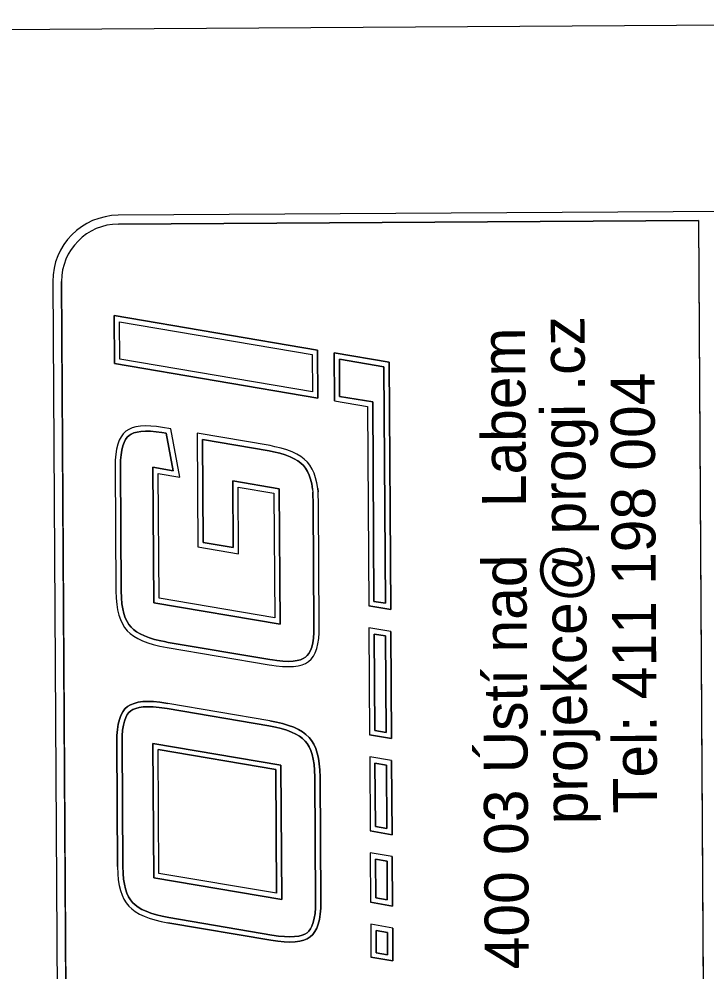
# Model space of a CAD drawing. Extents: x -735036 to -734743, y -1144813 to -1144181.
# Drawn here: x -734820.65 to -734790.92, y -1144221.87 to -1144180.65 of the extents above; entities that cross this region are included whole.
import ezdxf

# ---------------------------------------------------------------- set-up
doc = ezdxf.new("R2010")
doc.units = 0
doc.layers.add('000_rozpiska', color=7, linetype='Continuous')

# ---------------------------------------------------------------- blocks, each defined once
blk = doc.blocks.new('A$C2B726605')
at = {"layer": '000_rozpiska'}
for p, q in [((-8.894, 71.716), (-181.794, 71.716)), ((-8.894, 71.716), (-181.794, 71.716)), ((-8.894, 71.336), (-63.044, 71.336)), ((-34.759, 68.816), (-34.511, 68.836)), ((-34.511, 68.836), (-34.202, 68.844)), ((-34.202, 68.844), (-28.821, 68.844)), ((-28.821, 68.844), (-28.555, 68.837)), ((-28.555, 68.837), (-28.314, 68.816)), ((-23.536, 68.882), (-23.718, 68.8)), ((-23.336, 68.949), (-23.536, 68.882)), ((-23.113, 69), (-23.336, 68.949)), ((-22.876, 69.037), (-23.113, 69)), ((-22.611, 69.06), (-22.876, 69.037)), ((-22.599, 68.832), (-22.849, 68.811)), ((-22.293, 69.067), (-22.611, 69.06)), ((-22.29, 68.839), (-22.599, 68.832)), ((-16.9, 69.067), (-22.293, 69.067)), ((-16.903, 68.839), (-22.29, 68.839)), ((-16.644, 68.832), (-16.903, 68.839)), ((-16.631, 69.06), (-16.9, 69.067)), ((-16.41, 68.812), (-16.644, 68.832)), ((-16.382, 69.039), (-16.631, 69.06)), ((-16.158, 69.003), (-16.382, 69.039)), ((-15.946, 68.95), (-16.158, 69.003)), ((-15.774, 68.885), (-15.946, 68.95)), ((-15.623, 68.805), (-15.774, 68.885)), ((-14.003, 60.287), (-12.456, 69.067)), ((-13.731, 60.515), (-12.264, 68.839)), ((-12.456, 69.067), (-10.382, 69.067)), ((-12.264, 68.839), (-10.654, 68.839)), ((-10.654, 68.839), (-12.121, 60.515)), ((-10.382, 69.067), (-11.929, 60.287)), ((-6.424, 43.784), (-6.424, 68.866)), ((-6.044, 8.894), (-6.044, 68.866)), ((-6.044, 8.894), (-6.044, 68.866)), ((-35.877, 68.32), (-35.774, 68.43)), ((-35.774, 68.43), (-35.655, 68.523)), ((-35.655, 68.523), (-35.523, 68.603)), ((-35.523, 68.603), (-35.366, 68.674)), ((-35.366, 68.674), (-35.185, 68.734)), ((-35.185, 68.734), (-34.983, 68.781)), ((-34.983, 68.781), (-34.759, 68.816)), ((-28.314, 68.816), (-28.102, 68.782)), ((-28.102, 68.782), (-27.922, 68.735)), ((-27.922, 68.735), (-27.774, 68.68)), ((-27.774, 68.68), (-27.647, 68.612)), ((-27.647, 68.612), (-27.556, 68.541)), ((-27.556, 68.541), (-27.482, 68.458)), ((-27.482, 68.458), (-27.424, 68.363)), ((-24.14, 68.463), (-24.252, 68.312)), ((-24.014, 68.594), (-24.14, 68.463)), ((-23.875, 68.705), (-24.014, 68.594)), ((-23.86, 68.425), (-23.966, 68.315)), ((-23.718, 68.8), (-23.875, 68.705)), ((-23.744, 68.517), (-23.86, 68.425)), ((-23.612, 68.597), (-23.744, 68.517)), ((-23.453, 68.67), (-23.612, 68.597)), ((-23.274, 68.729), (-23.453, 68.67)), ((-23.07, 68.776), (-23.274, 68.729)), ((-22.849, 68.811), (-23.07, 68.776)), ((-16.203, 68.779), (-16.41, 68.812)), ((-16.014, 68.732), (-16.203, 68.779)), ((-15.868, 68.677), (-16.014, 68.732)), ((-15.744, 68.612), (-15.868, 68.677)), ((-15.646, 68.54), (-15.744, 68.612)), ((-15.57, 68.458), (-15.646, 68.54)), ((-15.494, 68.711), (-15.623, 68.805)), ((-15.513, 68.368), (-15.57, 68.458)), ((-15.389, 68.598), (-15.494, 68.711)), ((-15.31, 68.474), (-15.389, 68.598)), ((-15.247, 68.325), (-15.31, 68.474)), ((-36.158, 67.849), (-36.072, 68.03)), ((-36.072, 68.03), (-35.977, 68.188)), ((-35.977, 68.188), (-35.877, 68.32)), ((-27.424, 68.363), (-27.377, 68.245)), ((-27.377, 68.245), (-27.339, 68.093)), ((-27.339, 68.093), (-27.316, 67.921)), ((-24.358, 68.136), (-24.456, 67.934)), ((-24.252, 68.312), (-24.358, 68.136)), ((-24.157, 68.028), (-24.247, 67.843)), ((-24.062, 68.185), (-24.157, 68.028)), ((-23.966, 68.315), (-24.062, 68.185)), ((-15.462, 68.25), (-15.513, 68.368)), ((-15.425, 68.113), (-15.462, 68.25)), ((-15.401, 67.946), (-15.425, 68.113)), ((-15.201, 68.16), (-15.247, 68.325)), ((-15.174, 67.968), (-15.201, 68.16)), ((-36.313, 67.406), (-36.24, 67.64)), ((-36.24, 67.64), (-36.158, 67.849)), ((-27.309, 67.715), (-27.318, 67.49)), ((-27.316, 67.921), (-27.309, 67.715)), ((-24.542, 67.709), (-24.617, 67.47)), ((-24.456, 67.934), (-24.542, 67.709)), ((-24.327, 67.634), (-24.398, 67.408)), ((-24.247, 67.843), (-24.327, 67.634)), ((-15.39, 67.746), (-15.401, 67.946)), ((-15.396, 67.53), (-15.39, 67.746)), ((-15.161, 67.749), (-15.174, 67.968)), ((-15.168, 67.516), (-15.161, 67.749)), ((-36.377, 67.15), (-36.313, 67.406)), ((-35.686, 61.98), (-34.711, 67.51)), ((-35.414, 62.208), (-34.52, 67.282)), ((-34.711, 67.51), (-28.895, 67.51)), ((-34.52, 67.282), (-29.166, 67.282)), ((-30.06, 62.208), (-29.166, 67.282)), ((-29.869, 61.98), (-28.895, 67.51)), ((-27.343, 67.228), (-27.394, 66.891)), ((-27.318, 67.49), (-27.343, 67.228)), ((-24.689, 67.189), (-24.723, 67.024)), ((-24.617, 67.47), (-24.689, 67.189)), ((-24.398, 67.408), (-24.466, 67.138)), ((-23.773, 61.981), (-22.812, 67.436)), ((-23.501, 62.209), (-22.62, 67.208)), ((-22.812, 67.436), (-16.956, 67.436)), ((-22.62, 67.208), (-17.227, 67.208)), ((-17.227, 67.208), (-17.39, 66.281)), ((-16.956, 67.436), (-17.109, 66.562)), ((-15.455, 67.047), (-15.418, 67.292)), ((-15.418, 67.292), (-15.396, 67.53)), ((-15.23, 67.01), (-15.192, 67.265)), ((-15.192, 67.265), (-15.168, 67.516)), ((-37.443, 62.463), (-36.658, 66.917)), ((-37.218, 62.426), (-36.434, 66.871)), ((-36.434, 66.871), (-36.377, 67.15)), ((-27.394, 66.891), (-28.17, 62.485)), ((-27.946, 62.446), (-27.168, 66.857)), ((-24.755, 66.868), (-25.53, 62.465)), ((-24.531, 66.825), (-25.305, 62.43)), ((-24.723, 67.024), (-24.755, 66.868)), ((-24.499, 66.978), (-24.531, 66.825)), ((-24.466, 67.138), (-24.499, 66.978)), ((-17.109, 66.562), (-15.489, 66.851)), ((-15.489, 66.851), (-15.455, 67.047)), ((-15.293, 66.654), (-15.23, 67.01)), ((-17.39, 66.281), (-15.293, 66.654)), ((-20.41, 65.519), (-20.721, 63.755)), ((-20.219, 65.291), (-20.45, 63.983)), ((-15.492, 65.519), (-20.41, 65.519)), ((-15.764, 65.291), (-20.219, 65.291)), ((-16.272, 62.408), (-15.764, 65.291)), ((-16.049, 62.363), (-15.492, 65.519)), ((-20.45, 63.983), (-17.564, 63.983)), ((-17.564, 63.983), (-17.916, 61.981)), ((-20.721, 63.755), (-17.836, 63.755)), ((-17.836, 63.755), (-18.108, 62.209)), ((-37.262, 62.134), (-37.218, 62.426)), ((-28.168, 62.494), (-28.229, 62.211)), ((-25.547, 62.345), (-25.574, 62.154)), ((-25.53, 62.465), (-25.547, 62.345)), ((-25.321, 62.313), (-25.348, 62.126)), ((-25.305, 62.43), (-25.321, 62.313)), ((-16.316, 62.214), (-16.272, 62.408)), ((-16.095, 62.161), (-16.049, 62.363)), ((-37.298, 61.64), (-37.288, 61.87)), ((-37.288, 61.87), (-37.262, 62.134)), ((-35.686, 61.98), (-29.869, 61.98)), ((-35.414, 62.208), (-30.06, 62.208)), ((-28.289, 61.967), (-28.367, 61.72)), ((-28.229, 62.211), (-28.289, 61.967)), ((-25.602, 61.884), (-25.612, 61.64)), ((-25.574, 62.154), (-25.602, 61.884)), ((-25.375, 61.868), (-25.384, 61.64)), ((-25.348, 62.126), (-25.375, 61.868)), ((-17.916, 61.981), (-23.773, 61.981)), ((-18.108, 62.209), (-23.501, 62.209)), ((-16.456, 61.717), (-16.383, 61.95)), ((-16.383, 61.95), (-16.316, 62.214)), ((-16.241, 61.642), (-16.163, 61.888)), ((-16.163, 61.888), (-16.095, 62.161)), ((-37.291, 61.435), (-37.298, 61.64)), ((-37.268, 61.258), (-37.291, 61.435)), ((-28.448, 61.51), (-28.537, 61.326)), ((-28.367, 61.72), (-28.448, 61.51)), ((-25.612, 61.64), (-25.605, 61.413)), ((-25.605, 61.413), (-25.579, 61.21)), ((-25.384, 61.64), (-25.377, 61.431)), ((-25.377, 61.431), (-25.354, 61.252)), ((-16.626, 61.321), (-16.537, 61.505)), ((-16.537, 61.505), (-16.456, 61.717)), ((-16.426, 61.212), (-16.328, 61.415)), ((-16.328, 61.415), (-16.241, 61.642)), ((-37.231, 61.111), (-37.268, 61.258)), ((-37.184, 60.99), (-37.231, 61.111)), ((-28.729, 61.038), (-28.835, 60.928)), ((-28.63, 61.17), (-28.729, 61.038)), ((-28.537, 61.326), (-28.63, 61.17)), ((-25.579, 61.21), (-25.534, 61.032)), ((-25.534, 61.032), (-25.477, 60.887)), ((-25.354, 61.252), (-25.317, 61.102)), ((-25.317, 61.102), (-25.272, 60.989)), ((-16.924, 60.924), (-16.816, 61.036)), ((-16.816, 61.036), (-16.719, 61.167)), ((-16.719, 61.167), (-16.626, 61.321)), ((-16.642, 60.889), (-16.53, 61.04)), ((-16.53, 61.04), (-16.426, 61.212)), ((-37.126, 60.896), (-37.184, 60.99)), ((-37.055, 60.819), (-37.126, 60.896)), ((-36.959, 60.747), (-37.055, 60.819)), ((-36.839, 60.683), (-36.959, 60.747)), ((-36.687, 60.627), (-36.839, 60.683)), ((-36.506, 60.581), (-36.687, 60.627)), ((-29.421, 60.629), (-29.624, 60.582)), ((-29.242, 60.688), (-29.421, 60.629)), ((-29.082, 60.76), (-29.242, 60.688)), ((-28.949, 60.838), (-29.082, 60.76)), ((-28.835, 60.928), (-28.949, 60.838)), ((-25.477, 60.887), (-25.396, 60.755)), ((-25.396, 60.755), (-25.295, 60.643)), ((-25.295, 60.643), (-25.168, 60.55)), ((-25.272, 60.989), (-25.213, 60.893)), ((-25.213, 60.893), (-25.141, 60.813)), ((-25.141, 60.813), (-25.047, 60.744)), ((-25.047, 60.744), (-24.922, 60.677)), ((-24.922, 60.677), (-24.774, 60.621)), ((-24.774, 60.621), (-24.592, 60.576)), ((-17.714, 60.577), (-17.514, 60.623)), ((-17.514, 60.623), (-17.334, 60.683)), ((-17.334, 60.683), (-17.18, 60.751)), ((-17.18, 60.751), (-17.039, 60.833)), ((-17.076, 60.547), (-16.91, 60.645)), ((-17.039, 60.833), (-16.924, 60.924)), ((-16.91, 60.645), (-16.771, 60.755)), ((-16.771, 60.755), (-16.642, 60.889)), ((-36.295, 60.547), (-36.506, 60.581)), ((-36.059, 60.526), (-36.295, 60.547)), ((-35.746, 60.519), (-36.059, 60.526)), ((-30.401, 60.519), (-35.746, 60.519)), ((-30.095, 60.527), (-30.401, 60.519)), ((-29.849, 60.547), (-30.095, 60.527)), ((-29.624, 60.582), (-29.849, 60.547)), ((-25.168, 60.55), (-25.016, 60.469)), ((-25.016, 60.469), (-24.842, 60.403)), ((-24.842, 60.403), (-24.638, 60.353)), ((-24.638, 60.353), (-24.409, 60.316)), ((-24.592, 60.576), (-24.381, 60.543)), ((-24.409, 60.316), (-24.156, 60.295)), ((-24.381, 60.543), (-24.143, 60.522)), ((-24.156, 60.295), (-23.84, 60.287)), ((-24.143, 60.522), (-23.837, 60.515)), ((-23.84, 60.287), (-18.618, 60.287)), ((-23.837, 60.515), (-18.622, 60.515)), ((-18.622, 60.515), (-18.073, 60.532)), ((-18.618, 60.287), (-18.06, 60.305)), ((-17.938, 60.543), (-18.073, 60.532)), ((-17.912, 60.316), (-18.06, 60.305)), ((-17.938, 60.543), (-17.714, 60.577)), ((-17.912, 60.316), (-17.671, 60.353)), ((-17.671, 60.353), (-17.453, 60.403)), ((-17.453, 60.403), (-17.252, 60.47)), ((-17.252, 60.47), (-17.076, 60.547)), ((-11.929, 60.287), (-14.003, 60.287)), ((-12.121, 60.515), (-13.731, 60.515)), ((-14.128, 59.574), (-14.38, 58.143)), ((-14.128, 59.574), (-12.055, 59.574)), ((-12.055, 59.574), (-12.474, 57.193)), ((-13.937, 59.346), (-14.189, 57.915)), ((-13.937, 59.346), (-12.326, 59.346)), ((-12.326, 59.346), (-12.666, 57.421)), ((-38.371, 57.193), (-38.204, 58.143)), ((-36.779, 58.143), (-38.204, 58.143)), ((-36.946, 57.193), (-36.779, 58.143)), ((-35.996, 57.193), (-35.829, 58.143)), ((-33.691, 58.143), (-35.829, 58.143)), ((-33.859, 57.193), (-33.691, 58.143)), ((-32.909, 57.193), (-32.741, 58.143)), ((-29.535, 58.143), (-32.741, 58.143)), ((-29.702, 57.193), (-29.535, 58.143)), ((-28.752, 57.193), (-28.585, 58.143)), ((-23.954, 58.143), (-28.585, 58.143)), ((-24.121, 57.193), (-23.954, 58.143)), ((-23.171, 57.193), (-23.004, 58.143)), ((-14.38, 58.143), (-23.004, 58.143)), ((-38.099, 57.421), (-38.012, 57.915)), ((-37.05, 57.915), (-38.012, 57.915)), ((-37.137, 57.421), (-37.05, 57.915)), ((-35.724, 57.421), (-35.637, 57.915)), ((-33.963, 57.915), (-35.637, 57.915)), ((-34.05, 57.421), (-33.963, 57.915)), ((-32.637, 57.421), (-32.55, 57.915)), ((-29.807, 57.915), (-32.55, 57.915)), ((-29.894, 57.421), (-29.807, 57.915)), ((-28.481, 57.421), (-28.393, 57.915)), ((-24.225, 57.915), (-28.393, 57.915)), ((-24.312, 57.421), (-24.225, 57.915)), ((-22.899, 57.421), (-22.812, 57.915)), ((-14.189, 57.915), (-22.812, 57.915)), ((-37.137, 57.421), (-38.099, 57.421)), ((-34.05, 57.421), (-35.724, 57.421)), ((-29.894, 57.421), (-32.637, 57.421)), ((-24.312, 57.421), (-28.481, 57.421)), ((-12.666, 57.421), (-22.899, 57.421)), ((-36.946, 57.193), (-38.371, 57.193)), ((-33.859, 57.193), (-35.996, 57.193)), ((-29.702, 57.193), (-32.909, 57.193)), ((-24.121, 57.193), (-28.752, 57.193)), ((-12.474, 57.193), (-23.171, 57.193)), ((-6.424, 43.784), (-63.044, 43.784))]:
    blk.add_line(p, q, dxfattribs=at)
for points in [[(-63.044, 43.784), (-63.044, 71.336), (-8.894, 71.336)], [(-6.424, 68.866), (-6.424, 43.784), (-63.044, 43.784)], [(-28.055, 69.005), (-28.286, 69.042), (-28.542, 69.065), (-28.815, 69.072), (-34.205, 69.072), (-34.524, 69.064), (-34.786, 69.043), (-35.027, 69.005), (-35.246, 68.954), (-35.449, 68.887), (-35.629, 68.805), (-35.786, 68.711), (-35.928, 68.598), (-36.052, 68.467), (-36.166, 68.316), (-36.273, 68.138), (-36.368, 67.94), (-36.455, 67.716), (-36.532, 67.468), (-36.599, 67.2), (-36.658, 66.917), (-37.443, 62.463), (-37.489, 62.162), (-37.516, 61.886), (-37.526, 61.641), (-37.518, 61.417), (-37.493, 61.216), (-37.449, 61.041), (-37.388, 60.887), (-37.309, 60.758), (-37.209, 60.649), (-37.082, 60.554), (-36.933, 60.474), (-36.755, 60.409), (-36.552, 60.357), (-36.323, 60.321), (-36.071, 60.299), (-35.752, 60.291), (-30.398, 60.291), (-30.083, 60.299), (-29.822, 60.321), (-29.581, 60.358), (-29.359, 60.41), (-29.16, 60.475), (-28.977, 60.557), (-28.82, 60.65), (-28.682, 60.759), (-28.555, 60.89), (-28.441, 61.042), (-28.336, 61.217), (-28.238, 61.419), (-28.152, 61.644), (-28.07, 61.905), (-28.007, 62.16), (-27.946, 62.446), (-27.168, 66.857), (-27.117, 67.2), (-27.09, 67.475), (-27.081, 67.715), (-27.089, 67.94), (-27.115, 68.135), (-27.159, 68.315), (-27.219, 68.465), (-27.298, 68.595), (-27.4, 68.709), (-27.523, 68.804), (-27.68, 68.888), (-27.853, 68.953), (-28.055, 69.005)], [(-27.309, 67.715), (-27.316, 67.921), (-27.339, 68.093), (-27.377, 68.245), (-27.424, 68.363), (-27.482, 68.458), (-27.556, 68.541), (-27.647, 68.612), (-27.774, 68.68), (-27.922, 68.735), (-28.102, 68.782), (-28.314, 68.816), (-28.555, 68.837), (-28.821, 68.844), (-34.202, 68.844), (-34.511, 68.836), (-34.759, 68.816), (-34.983, 68.781), (-35.185, 68.734), (-35.366, 68.674), (-35.523, 68.603), (-35.655, 68.523), (-35.774, 68.43), (-35.877, 68.32), (-35.977, 68.188), (-36.072, 68.03), (-36.158, 67.849), (-36.24, 67.64), (-36.313, 67.406), (-36.377, 67.15), (-36.434, 66.871), (-37.218, 62.426), (-37.262, 62.134), (-37.288, 61.87), (-37.298, 61.64), (-37.291, 61.435), (-37.268, 61.258), (-37.231, 61.111), (-37.184, 60.99), (-37.126, 60.896), (-37.055, 60.819), (-36.959, 60.747), (-36.839, 60.683), (-36.687, 60.627), (-36.506, 60.581), (-36.295, 60.547), (-36.059, 60.526), (-35.746, 60.519), (-30.401, 60.519), (-30.095, 60.527), (-29.849, 60.547), (-29.624, 60.582), (-29.421, 60.629), (-29.242, 60.688), (-29.082, 60.76), (-28.949, 60.838), (-28.835, 60.928), (-28.729, 61.038), (-28.63, 61.17), (-28.537, 61.326), (-28.448, 61.51), (-28.367, 61.72), (-28.289, 61.967), (-28.229, 62.211), (-28.169, 62.489), (-27.394, 66.891), (-27.343, 67.228), (-27.318, 67.49), (-27.309, 67.715)], [(-28.821, 68.844), (-28.555, 68.837), (-28.314, 68.816), (-28.102, 68.782), (-27.922, 68.735), (-27.774, 68.68), (-27.647, 68.612), (-27.556, 68.541), (-27.482, 68.458), (-27.424, 68.363), (-27.377, 68.245), (-27.339, 68.093), (-27.316, 67.921), (-27.309, 67.715), (-27.318, 67.49), (-27.343, 67.228), (-27.394, 66.891), (-28.169, 62.489), (-28.229, 62.211), (-28.289, 61.967), (-28.367, 61.72), (-28.448, 61.51), (-28.537, 61.326), (-28.63, 61.17), (-28.729, 61.038), (-28.835, 60.928), (-28.949, 60.838), (-29.082, 60.76), (-29.242, 60.688), (-29.421, 60.629), (-29.624, 60.582), (-29.849, 60.547), (-30.095, 60.527), (-30.401, 60.519), (-35.746, 60.519), (-36.059, 60.526), (-36.295, 60.547), (-36.506, 60.581), (-36.687, 60.627), (-36.839, 60.683), (-36.959, 60.747), (-37.055, 60.819), (-37.126, 60.896), (-37.184, 60.99), (-37.231, 61.111), (-37.268, 61.258), (-37.291, 61.435), (-37.298, 61.64), (-37.288, 61.87), (-37.262, 62.134), (-37.218, 62.426), (-36.434, 66.871), (-36.377, 67.15), (-36.313, 67.406), (-36.24, 67.64), (-36.158, 67.849), (-36.072, 68.03), (-35.977, 68.188), (-35.877, 68.32), (-35.774, 68.43), (-35.655, 68.523), (-35.523, 68.603), (-35.366, 68.674), (-35.185, 68.734), (-34.983, 68.781), (-34.759, 68.816), (-34.511, 68.836), (-34.202, 68.844), (-28.821, 68.844)], [(-34.205, 69.072), (-34.524, 69.064), (-34.786, 69.043), (-35.027, 69.005), (-35.246, 68.954), (-35.449, 68.887), (-35.629, 68.805), (-35.786, 68.711), (-35.928, 68.598), (-36.052, 68.467), (-36.166, 68.316), (-36.273, 68.138), (-36.368, 67.94), (-36.455, 67.716), (-36.532, 67.468), (-36.599, 67.2), (-36.658, 66.917)], [(-34.205, 69.072), (-28.815, 69.072), (-28.542, 69.065), (-28.286, 69.042), (-28.055, 69.005), (-27.853, 68.953), (-27.68, 68.888), (-27.523, 68.804), (-27.4, 68.709), (-27.298, 68.595), (-27.219, 68.465), (-27.159, 68.315), (-27.115, 68.135), (-27.089, 67.94), (-27.081, 67.715), (-27.09, 67.475), (-27.117, 67.2), (-27.168, 66.857)], [(-15.946, 68.95), (-16.158, 69.003), (-16.382, 69.039), (-16.631, 69.06), (-16.9, 69.067), (-22.293, 69.067), (-22.611, 69.06), (-22.876, 69.037), (-23.113, 69), (-23.336, 68.949), (-23.536, 68.882), (-23.718, 68.8), (-23.875, 68.705), (-24.014, 68.594), (-24.14, 68.463), (-24.252, 68.312), (-24.358, 68.136), (-24.456, 67.934), (-24.542, 67.709), (-24.617, 67.47), (-24.689, 67.189), (-24.723, 67.024), (-24.755, 66.868), (-25.53, 62.465), (-25.547, 62.345), (-25.574, 62.154), (-25.602, 61.884), (-25.612, 61.64), (-25.605, 61.413), (-25.579, 61.21), (-25.534, 61.032), (-25.477, 60.887), (-25.396, 60.755), (-25.295, 60.643), (-25.168, 60.55), (-25.016, 60.469), (-24.842, 60.403), (-24.638, 60.353), (-24.409, 60.316), (-24.156, 60.295), (-23.84, 60.287), (-18.618, 60.287), (-18.06, 60.305), (-17.912, 60.316), (-17.671, 60.353), (-17.453, 60.403), (-17.252, 60.47), (-17.076, 60.547), (-16.91, 60.645), (-16.771, 60.755), (-16.642, 60.889), (-16.53, 61.04), (-16.426, 61.212), (-16.328, 61.415), (-16.241, 61.642), (-16.163, 61.888), (-16.095, 62.161), (-16.049, 62.363), (-15.492, 65.519), (-20.41, 65.519), (-20.721, 63.755), (-17.836, 63.755), (-18.108, 62.209), (-23.501, 62.209), (-22.62, 67.208), (-17.227, 67.208), (-17.39, 66.281), (-15.293, 66.654), (-15.23, 67.01), (-15.192, 67.265), (-15.168, 67.516), (-15.161, 67.749), (-15.174, 67.968), (-15.201, 68.16), (-15.247, 68.325), (-15.31, 68.474), (-15.389, 68.598), (-15.494, 68.711), (-15.623, 68.805), (-15.774, 68.885), (-15.946, 68.95)], [(-16.903, 68.839), (-16.644, 68.832), (-16.41, 68.812), (-16.203, 68.779), (-16.014, 68.732), (-15.868, 68.677), (-15.744, 68.612), (-15.646, 68.54), (-15.57, 68.458), (-15.513, 68.368), (-15.462, 68.25), (-15.425, 68.113), (-15.401, 67.946), (-15.39, 67.746), (-15.396, 67.53), (-15.418, 67.292), (-15.455, 67.047), (-15.489, 66.851), (-17.109, 66.562), (-16.956, 67.436), (-22.812, 67.436), (-23.773, 61.981), (-17.916, 61.981), (-17.564, 63.983), (-20.45, 63.983), (-20.219, 65.291), (-15.764, 65.291), (-16.272, 62.408), (-16.316, 62.214), (-16.383, 61.95), (-16.456, 61.717), (-16.537, 61.505), (-16.626, 61.321), (-16.719, 61.167), (-16.816, 61.036), (-16.924, 60.924), (-17.039, 60.833), (-17.18, 60.751), (-17.334, 60.683), (-17.514, 60.623), (-17.714, 60.577), (-17.938, 60.543), (-18.073, 60.532), (-18.622, 60.515), (-23.837, 60.515), (-24.143, 60.522), (-24.381, 60.543), (-24.592, 60.576), (-24.774, 60.621), (-24.922, 60.677), (-25.047, 60.744), (-25.141, 60.813), (-25.213, 60.893), (-25.272, 60.989), (-25.317, 61.102), (-25.354, 61.252), (-25.377, 61.431), (-25.384, 61.64), (-25.375, 61.868), (-25.348, 62.126), (-25.321, 62.313), (-25.305, 62.43), (-24.531, 66.825), (-24.499, 66.978), (-24.466, 67.138), (-24.398, 67.408), (-24.327, 67.634), (-24.247, 67.843), (-24.157, 68.028), (-24.062, 68.185), (-23.966, 68.315), (-23.86, 68.425), (-23.744, 68.517), (-23.612, 68.597), (-23.453, 68.67), (-23.274, 68.729), (-23.07, 68.776), (-22.849, 68.811), (-22.599, 68.832), (-22.29, 68.839), (-16.903, 68.839)], [(-10.382, 69.067), (-12.456, 69.067), (-14.003, 60.287), (-11.929, 60.287), (-10.382, 69.067)], [(-10.654, 68.839), (-12.121, 60.515), (-13.731, 60.515), (-12.264, 68.839), (-10.654, 68.839)], [(-28.895, 67.51), (-29.869, 61.98), (-35.686, 61.98), (-34.711, 67.51), (-28.895, 67.51)], [(-28.895, 67.51), (-34.711, 67.51), (-35.686, 61.98), (-29.869, 61.98), (-28.895, 67.51)], [(-29.166, 67.282), (-30.06, 62.208), (-35.414, 62.208), (-34.52, 67.282), (-29.166, 67.282)], [(-35.752, 60.291), (-36.071, 60.299), (-36.323, 60.321), (-36.552, 60.357), (-36.755, 60.409), (-36.933, 60.474), (-37.082, 60.554), (-37.209, 60.649), (-37.309, 60.758), (-37.388, 60.887), (-37.449, 61.041), (-37.493, 61.216), (-37.518, 61.417), (-37.526, 61.641), (-37.516, 61.886), (-37.489, 62.162), (-37.443, 62.463)], [(-27.946, 62.446), (-28.007, 62.16), (-28.07, 61.905), (-28.152, 61.644), (-28.238, 61.419), (-28.336, 61.217), (-28.441, 61.042), (-28.555, 60.89), (-28.682, 60.759), (-28.82, 60.65), (-28.977, 60.557), (-29.16, 60.475), (-29.359, 60.41), (-29.581, 60.358), (-29.822, 60.321), (-30.083, 60.299), (-30.398, 60.291), (-35.752, 60.291)], [(-12.055, 59.574), (-14.128, 59.574), (-14.38, 58.143), (-23.004, 58.143), (-23.171, 57.193), (-12.474, 57.193), (-12.055, 59.574)], [(-12.326, 59.346), (-12.666, 57.421), (-22.899, 57.421), (-22.812, 57.915), (-14.189, 57.915), (-13.937, 59.346), (-12.326, 59.346)], [(-12.326, 59.346), (-13.937, 59.346), (-14.189, 57.915), (-22.812, 57.915), (-22.899, 57.421), (-12.666, 57.421), (-12.326, 59.346)], [(-36.779, 58.143), (-38.204, 58.143), (-38.371, 57.193), (-36.946, 57.193), (-36.779, 58.143)], [(-33.691, 58.143), (-35.829, 58.143), (-35.996, 57.193), (-33.859, 57.193), (-33.691, 58.143)], [(-29.535, 58.143), (-32.741, 58.143), (-32.909, 57.193), (-29.702, 57.193), (-29.535, 58.143)], [(-23.954, 58.143), (-28.585, 58.143), (-28.752, 57.193), (-24.121, 57.193), (-23.954, 58.143)], [(-37.05, 57.915), (-37.137, 57.421), (-38.099, 57.421), (-38.012, 57.915), (-37.05, 57.915)], [(-37.05, 57.915), (-38.012, 57.915), (-38.099, 57.421), (-37.137, 57.421), (-37.05, 57.915)], [(-33.963, 57.915), (-34.05, 57.421), (-35.724, 57.421), (-35.637, 57.915), (-33.963, 57.915)], [(-33.963, 57.915), (-35.637, 57.915), (-35.724, 57.421), (-34.05, 57.421), (-33.963, 57.915)], [(-29.807, 57.915), (-29.894, 57.421), (-32.637, 57.421), (-32.55, 57.915), (-29.807, 57.915)], [(-29.807, 57.915), (-32.55, 57.915), (-32.637, 57.421), (-29.894, 57.421), (-29.807, 57.915)], [(-24.225, 57.915), (-24.312, 57.421), (-28.481, 57.421), (-28.393, 57.915), (-24.225, 57.915)], [(-24.225, 57.915), (-28.393, 57.915), (-28.481, 57.421), (-24.312, 57.421), (-24.225, 57.915)]]:
    blk.add_lwpolyline(points, dxfattribs=at)
for radius, start in [(2.85, 0), (2.85, 360), (2.47, 0), (2.47, 360)]:
    blk.add_arc((-8.894, 68.866), radius, start, 90, dxfattribs=at)
for s, p in [('400 03 Ústí nad', (-38.76, 51.316)), ('Labem', (-18.775, 51.316)), ('projekce@', (-32.507, 48.739)), ('progi', (-19.971, 48.739)), ('.cz', (-13.774, 48.739)), ('Tel: 411 198 004', (-32.058, 45.729))]:
    blk.add_text(s, height=1.9, dxfattribs=at).set_placement(p)

msp = doc.modelspace()

# ---------------------------------------------------------------- linework, layer by layer
at = {"layer": '000_rozpiska'}
msp.add_line((-734746.942, -1144180.653), (-735035.936, -1144182.44), dxfattribs=at)

# ---------------------------------------------------------------- block references
at = {"layer": '000_rozpiska', "rotation": 90.35414249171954}
msp.add_blockref('A$C2B726605', (-734747.538, -1144182.67), dxfattribs=at)

doc.saveas('drawing.dxf')
